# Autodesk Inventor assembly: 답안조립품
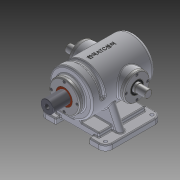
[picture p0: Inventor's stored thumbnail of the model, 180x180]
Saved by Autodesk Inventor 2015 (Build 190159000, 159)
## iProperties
Created: 2015-10
Part Number: 답안조립품
Document SubType Name: Assembly
Designer: youjin09
Mass: 9437.34 g
Surface Area: 4327.32 cm^2
Volume: 2315.26 cm^3
Density: 4.07615 g/cm^3
Author: youjin09
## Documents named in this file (13)
- C:\Users\youjin09\Desktop\351019V1014\답안조립품.iam
- C:\Users\youjin09\Desktop\351019V1014\본체.ipt
- C:\Users\youjin09\Desktop\351019V1014\축 커버.ipt
- C:\Users\youjin09\Desktop\351019V1014\슬라이드 커버.ipt
- C:\Users\youjin09\Desktop\351019V1014\M4x0.7.ipt
- C:\Users\youjin09\Desktop\351019V1014\오일실.ipt
- 오일실.ipt
- C:\Users\youjin09\Desktop\351019V1014\베어링 6205.ipt
- 베어링 6205.ipt
- C:\Users\youjin09\Desktop\351019V1014\편심축.ipt
- C:\Users\youjin09\Desktop\351019V1014\부시.ipt
- C:\Users\youjin09\Desktop\351019V1014\가변스프링.ipt
- C:\Users\youjin09\Desktop\351019V1014\슬라이드.ipt
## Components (13 placed, 2 different names)
1. 가변스프링:1 — Mate:22, Mate:23, Mate:24, Mate:25
2. M4x0.7:3 — Insert:1
3. M4x0.7:4
4. M4x0.7:5
5. M4x0.7:6
6. M4x0.7:2 — Insert:3
7. M4x0.7:7
8. M4x0.7:8
9. M4x0.7:9
10. M4x0.7:1 — Insert:2
11. M4x0.7:10
12. M4x0.7:11
13. M4x0.7:12
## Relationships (7: Mate 4, Insert 3)
- Insert:1: M4x0.7:3
- Insert:2: M4x0.7:1
- Insert:3: M4x0.7:2
- Mate:22: 가변스프링:1
- Mate:23: 가변스프링:1
- Mate:24: 가변스프링:1
- Mate:25: 가변스프링:1
